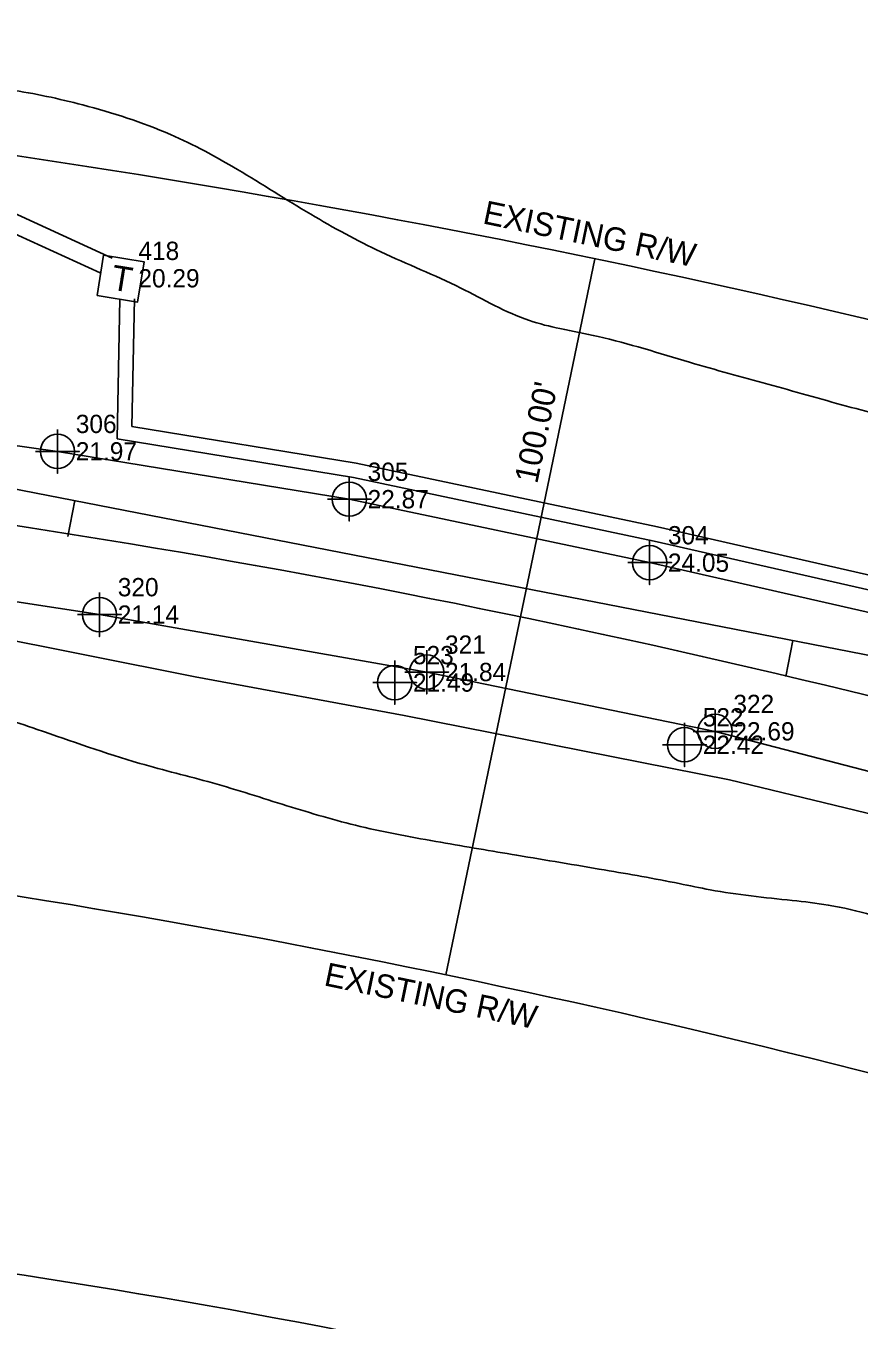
# Model space of a CAD drawing. Extents: x 2627243 to 2636458, y 566398 to 571062.
# Drawn here: x 2634899.6 to 2635013.5, y 568953.4 to 569130.3 of the extents above; entities that cross this region are included whole.
import ezdxf

# ---------------------------------------------------------------- set-up
doc = ezdxf.new("R2010")
doc.units = 0
for name, color, linetype in [('COGO Default Chain', 7, 'Continuous'), ('COGO Default Curve', 7, 'Continuous'), ('Exist Horizontal Alignment', 7, 'Continuous'), ('Exist Horizontal Baseline Alignment', 7, 'Continuous'), ('Exist Horizontal Baseline Alignment Tick small', 7, 'Continuous'), ('Exist Right of Way Line', 7, 'Continuous'), ('Exist Right of Way Line Text', 7, 'Continuous'), ('Exist Right of Way Width CELL', 7, 'Continuous'), ('Exist Roads EOP', 7, 'Continuous'), ('Exist Roads EOP Cogo Elevation', 7, 'Continuous'), ('Exist Roads EOP Cogo Number', 7, 'Continuous'), ('Exist Roads EOP Cogo Point CELL', 7, 'Continuous'), ('Exist Utilities Telephone Pedestal CELL', 7, 'Continuous'), ('Exist Utilities Telephone Pedestal Cogo Elevation', 7, 'Continuous'), ('Exist Utilities Telephone Pedestal Cogo Number', 7, 'Continuous'), ('Exist Utilities Telephone UG Cable', 7, 'Continuous'), ('Exist Utilities Water UG Line Cogo Elevation', 7, 'Continuous'), ('Exist Utilities Water UG Line Cogo Number', 7, 'Continuous'), ('Exist Utilities Water UG Line Cogo Point CELL', 7, 'Continuous'), ('Exist Utilities Water UG Line SUE', 7, 'Continuous'), ('Exist Vegetation Woods Line', 7, 'Continuous'), ('Scratch_Level_2', 7, 'Continuous')]:
    doc.layers.add(name, color=color, linetype=linetype)

# ---------------------------------------------------------------- blocks, each defined once
blk = doc.blocks.new('EXIST ROADS EOP COGO POINT')
at = {"layer": 'Exist Roads EOP Cogo Point CELL'}
blk.add_lwpolyline([(0, 0.06), (0, -0.06), (0, 0), (0.06, 0), (-0.06, 0)], dxfattribs=at)
blk.add_circle((0, 0), 0.0469, dxfattribs=at)
blk = doc.blocks.new('EXIST UTILITIES TELEPHONE PEDESTAL')
at = {"layer": 'Exist Utilities Telephone Pedestal CELL'}
blk.add_line((0, 0), (0, 0), dxfattribs=at)
blk.add_lwpolyline([(-0.0545, -0.0565), (0.0574, -0.0565), (0.0574, 0.0554), (-0.0545, 0.0554), (-0.0545, -0.0565)], dxfattribs=at)
blk.add_text('T', height=0.0684, dxfattribs=at).set_placement((-0.0226, -0.0343))
blk = doc.blocks.new('EXIST UTILITIES WATER UG LINE COGO POINT')
at = {"layer": 'Exist Utilities Water UG Line Cogo Point CELL'}
blk.add_lwpolyline([(0, 0.06), (0, -0.06), (0, 0), (0.06, 0), (-0.06, 0)], dxfattribs=at)
blk.add_circle((0, 0), 0.0469, dxfattribs=at)

msp = doc.modelspace()

# ---------------------------------------------------------------- linework, layer by layer
at = {"layer": 'COGO Default Chain'}
msp.add_arc((2634692.38, 567727.8), 1350, 72.91185, 82.32218, dxfattribs=at)
msp.add_arc((2634692.38, 567727.8), 1350, 72.91185, 82.32218, dxfattribs=at)
at = {"layer": 'COGO Default Curve'}
msp.add_arc((2634692.38, 567727.8), 1350, 72.91185, 82.32218, dxfattribs=at)
at = {"layer": 'Exist Horizontal Alignment'}
msp.add_arc((2634692.38, 567727.8), 1350, 72.91185, 82.32218, dxfattribs=at)
at = {"layer": 'Exist Horizontal Baseline Alignment'}
msp.add_line((2634680.61, 569109.43), (2635129.79, 569021.83), dxfattribs=at)
at = {"layer": 'Exist Horizontal Baseline Alignment Tick small'}
for p, q in [((2634906.25, 569065.43), (2634905.29, 569060.52)), ((2635004.4, 569046.29), (2635003.44, 569041.38))]:
    msp.add_line(p, q, dxfattribs=at)
at = {"layer": 'Exist Right of Way Line'}
for radius in [1400, 1300]:
    msp.add_arc((2634692.38, 567727.8), radius, 72.91185, 82.32218, dxfattribs=at)
at = {"layer": 'Exist Right of Way Width CELL'}
for p in [(2634977.34, 569098.49), (2634956.99, 569000.59)]:
    msp.add_line(p, (2634967.39, 569050.61), dxfattribs=at)
at = {"layer": 'Exist Roads EOP'}
for points in [[(2635150.9, 569010.29), (2635110.64, 569022.78), (2635067.86, 569035.57), (2635023.64, 569048.11), (2634984.83, 569056.94), (2634943.78, 569065.62), (2634903.89, 569072.15), (2634856.98, 569078.75), (2634806.21, 569085.47), (2634756.15, 569092.13), (2634708.47, 569098.26)], [(2634739.19, 569072.43), (2634781.28, 569066.95), (2634828.08, 569061.02), (2634863.8, 569056.89), (2634909.63, 569049.84), (2634954.36, 569041.99), (2634993.78, 569033.88), (2635035.22, 569023.11), (2635076.05, 569011.42), (2635118.47, 568998.14), (2635130.61, 568994.63)]]:
    msp.add_lwpolyline(points, dxfattribs=at)
at = {"layer": 'Exist Utilities Telephone UG Cable'}
for p, q in [((2634864.77, 569119.93), (2634911.34, 569098.58)), ((2634914.4, 569092.99), (2634914.07, 569075.55))]:
    msp.add_line(p, q, dxfattribs=at)
for points in [[(2634863.43, 569117.69), (2634909.73, 569096.55)], [(2634912.4, 569092.99), (2634912.04, 569073.86)], [(2634914.07, 569075.55), (2634944.7, 569070.54), (2634985.9, 569061.82), (2635024.88, 569052.96), (2635069.26, 569040.37), (2635112.09, 569027.56), (2635152.41, 569015.06), (2635241.49, 568986.31)], [(2634912.04, 569073.86), (2634944.33, 569068.57), (2634985.47, 569059.87), (2635024.38, 569051.02), (2635068.7, 569038.45), (2635111.51, 569025.65), (2635151.81, 569013.15), (2635242.78, 568983.79)]]:
    msp.add_lwpolyline(points, dxfattribs=at)
at = {"layer": 'Exist Utilities Water UG Line SUE'}
msp.add_lwpolyline([(2634745.29, 569060.81), (2634772.3, 569060.34), (2634799.29, 569058.16), (2634834.92, 569055.15), (2634876.42, 569050.41), (2634893.17, 569047.22), (2634922.73, 569041.34), (2634951.3, 569036.03), (2634995.75, 569027.26), (2635043.17, 569015.78), (2635070.42, 569008.3), (2635098.21, 568999.23), (2635119.9, 568992.52), (2635152.3, 568983.11), (2635187.64, 568971.23), (2635214.87, 568960.8)], dxfattribs=at)
at = {"layer": 'Exist Vegetation Woods Line'}
for points in [[(2635649.22, 568878.38), (2635649.32, 568878.23), (2635637.74, 568881.93), (2635627.68, 568886.16), (2635617.49, 568889.28), (2635607.89, 568892.77), (2635596.11, 568897.78), (2635585.94, 568901.53), (2635574.03, 568905.43), (2635563.97, 568908.01), (2635552.13, 568911.13), (2635540.53, 568914.2), (2635528.58, 568918.49), (2635517.15, 568923.92), (2635505.87, 568929.45), (2635493.79, 568934.28), (2635482.45, 568937.92), (2635472.8, 568941.17), (2635463.24, 568944.27), (2635450.66, 568948.58), (2635439.69, 568951.62), (2635428.91, 568954.37), (2635419.18, 568956.75), (2635408.99, 568959.87), (2635397.38, 568963.96), (2635387.75, 568967.84), (2635376.76, 568971.9), (2635365.81, 568975.58), (2635356.14, 568978.2), (2635343.89, 568980.65), (2635330.64, 568983.72), (2635319.31, 568987.36), (2635308.9, 568991.16), (2635296.37, 568995.71), (2635286.29, 568999.31), (2635275.75, 569003.66), (2635265.84, 569006.33), (2635254.74, 569009.92), (2635243.26, 569013.46), (2635232.29, 569016.51), (2635221.8, 569019.45), (2635210.06, 569022.42), (2635198.81, 569025.91), (2635186.75, 569029.72), (2635176, 569033.73), (2635165.13, 569036.63), (2635154.25, 569039.52), (2635143.19, 569042.72), (2635132.43, 569046.1), (2635121.91, 569049.42), (2635110.35, 569053.75), (2635098.3, 569058.19), (2635086.72, 569061.88), (2635075.7, 569064.69), (2635065.45, 569065.92), (2635055.37, 569067.87), (2635043.05, 569071.1), (2635032.79, 569073.35), (2635022.28, 569075.66), (2635011.74, 569078.35), (2635001.01, 569081.34), (2634990.29, 569084.33), (2634977.78, 569087.86), (2634972.57, 569088.94), (2634968.39, 569090.04), (2634959.01, 569094.49), (2634948.1, 569099.43), (2634938.51, 569104.57), (2634928.51, 569110.69), (2634919.34, 569115.47), (2634907.33, 569119.52), (2634897.4, 569121.57), (2634887.58, 569122.45)], [(2634884.26, 569038.05), (2634886.56, 569037.01), (2634891.39, 569036.52), (2634901.12, 569034.15), (2634915.14, 569029.5), (2634925.06, 569026.83), (2634935.25, 569023.71), (2634945.25, 569020.89), (2634956.29, 569018.71), (2634966.67, 569016.94), (2634978.64, 569014.93), (2634988.87, 569013.07), (2634993.11, 569012.22), (2635004.32, 569010.76), (2635009.25, 569010.13), (2635021.09, 569007.01), (2635032.91, 569003.26), (2635042.45, 568999.53), (2635053.53, 568995.31), (2635059.94, 568992.31), (2635063.96, 568988.84), (2635068.1, 568983.18), (2635069.84, 568978.09), (2635070.85, 568973.16), (2635071.01, 568962.34), (2635071.84, 568951.11), (2635071.39, 568945.89), (2635069.32, 568935.33), (2635067.26, 568929.72), (2635061.77, 568919.7), (2635060.58, 568917.31), (2635058.33, 568907.05), (2635057.25, 568901.84), (2635053.76, 568892.25), (2635052.34, 568887.25), (2635051.59, 568875.24), (2635053.09, 568865.26), (2635053.64, 568861.07), (2635052.91, 568856.29), (2635050.59, 568850.1), (2635045.24, 568840.18), (2635043.57, 568836.25), (2635042.27, 568830.08), (2635042.12, 568825.04), (2635043.5, 568821.17), (2635048.99, 568819.65), (2635058.5, 568819.6), (2635060.79, 568818.56), (2635063.29, 568814.56), (2635064.54, 568804.63), (2635064.11, 568796.74), (2635061.15, 568785.62), (2635058.65, 568781.38), (2635057.09, 568779.59), (2635053.09, 568777.09), (2635050.58, 568776.14), (2635045.71, 568775.37), (2635041.48, 568775.21), (2635029.4, 568775.09), (2635024.38, 568774.22), (2635020.15, 568772.41), (2635018.11, 568770.72), (2635018.04, 568768.2), (2635020.42, 568763.72), (2635021.83, 568762.12), (2635031.48, 568755.58), (2635039.16, 568746.57), (2635043.88, 568740.65), (2635047.57, 568737.39), (2635049.1, 568735.26), (2635049.71, 568732.96), (2635048.56, 568728.53), (2635046.04, 568723.66), (2635041.88, 568721.07), (2635031.49, 568720.56), (2635029.24, 568720.19), (2635024.31, 568719.18), (2635017.66, 568718.94), (2635010.8, 568718.37), (2635006.37, 568717.87), (2635004.04, 568717.65), (2634992.51, 568716.64), (2634985.69, 568715.69), (2634974.53, 568714.08), (2634962.6, 568712.4), (2634952.4, 568710.58), (2634941.84, 568707.7), (2634930.51, 568705.37), (2634917.06, 568703.16), (2634903.7, 568700.8), (2634892.48, 568698.95), (2634880.79, 568697.22), (2634868.31, 568695.41), (2634858.45, 568693.38), (2634848.02, 568691.61), (2634837.58, 568689.84), (2634826.76, 568688.03)]]:
    msp.add_spline(points, degree=3, dxfattribs=at)
at = {"layer": 'Scratch_Level_2'}
for radius, start in [(1300, 71.85823), (1100, 71.68915)]:
    msp.add_arc((2634732.36, 567872.26), radius, start, 82.26155, dxfattribs=at)

# ---------------------------------------------------------------- block references
at = {"layer": 'Exist Roads EOP Cogo Point CELL', "xscale": 50, "yscale": 50}
for p in [(2634903.89, 569072.15), (2634943.78, 569065.62), (2634984.83, 569056.94), (2634909.63, 569049.84), (2634954.36, 569041.99), (2634993.78, 569033.88)]:
    msp.add_blockref('EXIST ROADS EOP COGO POINT', p, dxfattribs=at)
at = {"layer": 'Exist Utilities Telephone Pedestal CELL', "xscale": 50, "yscale": 50.00000000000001, "rotation": -9.138762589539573}
msp.add_blockref('EXIST UTILITIES TELEPHONE PEDESTAL', (2634912.45, 569095.81), dxfattribs=at)
at = {"layer": 'Exist Utilities Water UG Line Cogo Point CELL', "xscale": 50, "yscale": 50}
for p in [(2634949.98, 569040.55), (2634989.6, 569032.05)]:
    msp.add_blockref('EXIST UTILITIES WATER UG LINE COGO POINT', p, dxfattribs=at)

# ---------------------------------------------------------------- texts
at = {"layer": 'Exist Right of Way Line Text'}
for rotation, p in [(348.2645, (2634961.89, 569103.34)), (348.267, (2634940.19, 568999.17))]:
    msp.add_text('EXISTING R/W', height=3.2, rotation=rotation, dxfattribs=at).set_placement(p)
at = {"layer": 'Exist Right of Way Width CELL'}
msp.add_text("100.00'", height=3.2, rotation=78.2557, dxfattribs=at).set_placement((2634969.46, 569067.62))
at = {"layer": 'Exist Roads EOP Cogo Elevation'}
for s, p in [('21.97', (2634906.39, 569070.91)), ('22.87', (2634946.28, 569064.37)), ('24.05', (2634987.33, 569055.69)), ('21.14', (2634912.13, 569048.59)), ('21.84', (2634956.86, 569040.74)), ('22.69', (2634996.28, 569032.63))]:
    msp.add_text(s, height=2.5, dxfattribs=at).set_placement(p)
at = {"layer": 'Exist Roads EOP Cogo Number'}
for s, p in [('306', (2634906.39, 569074.66)), ('305', (2634946.28, 569068.12)), ('304', (2634987.33, 569059.44)), ('320', (2634912.13, 569052.34)), ('321', (2634956.86, 569044.49)), ('322', (2634996.28, 569036.38))]:
    msp.add_text(s, height=2.5, dxfattribs=at).set_placement(p)
at = {"layer": 'Exist Utilities Telephone Pedestal Cogo Elevation'}
msp.add_text('20.29', height=2.5, dxfattribs=at).set_placement((2634914.95, 569094.57))
at = {"layer": 'Exist Utilities Telephone Pedestal Cogo Number'}
msp.add_text('418', height=2.5, dxfattribs=at).set_placement((2634914.95, 569098.32))
at = {"layer": 'Exist Utilities Water UG Line Cogo Elevation'}
for s, p in [('21.49', (2634952.48, 569039.3)), ('22.42', (2634992.1, 569030.8))]:
    msp.add_text(s, height=2.5, dxfattribs=at).set_placement(p)
at = {"layer": 'Exist Utilities Water UG Line Cogo Number'}
for s, p in [('523', (2634952.48, 569043.05)), ('522', (2634992.1, 569034.55))]:
    msp.add_text(s, height=2.5, dxfattribs=at).set_placement(p)

doc.saveas('drawing.dxf')
